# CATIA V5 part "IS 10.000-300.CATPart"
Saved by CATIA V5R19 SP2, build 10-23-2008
Part number: IS 10.000-300
Bounding box of the stored display mesh (mm): x -97.324 to 97.324, y -97.5 to 97.5, z 0 to 760
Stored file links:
  C:\Users\Bora\Desktop\3D Katı model\IS serisi\IS 10.000\IS 10.000-300.CATPart
  C:\Program Files\Dassault Systemes\B19\intel_a\reffiles\standard\MetricThickPitch.txt
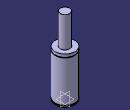
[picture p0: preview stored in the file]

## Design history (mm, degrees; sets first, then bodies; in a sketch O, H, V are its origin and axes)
Body1 (main body)
  Sketch1 on yz-plane, origin (0, 0, 0), H (0, 1, 0), V (0, 0, 1)
    point P1 (97.5, 429)
    point P4 (97.5, 424)
    point P7 (47.5, 759)
    point P9 (47.5, 759)
    point P13 (97.5, 429)
    point P14 (97.5, 424)
    line L1 (97.5, 429) -> (97.5, 457)
    line L2 (97.5, 16) -> (97.5, 424)
    line L3 (93.5, 16) -> (93.5, 8)
    arc A1 centre (46.5, 759) radius 1 from (47.5, 759) to (46.5, 760) ccw
    line L4 (47.5, 759) -> (47.5, 457)
    line L5 (97.5, 0) -> (97.5, 8)
    arc A2 centre (97.5, 426.5) radius 2.5 from (97.5, 429) to (97.5, 424) ccw
    line L6 (46.5, 760) -> (0, 760)
    point P15 (0, 760)
    line L7 (47.5, 457) -> (97.5, 457)
    line L8 (93.5, 16) -> (97.5, 16)
    line L9 (93.5, 8) -> (97.5, 8)
    line L10 (97.5, 0) -> (0, 0)
    tangency: L6 A1
    coincidence: P15 V, P1 P13, P4 P14, P7 P9
    horizontal: L7 H, L8 H, L9 H, L10 H
  Shaft1: profile Sketch1, axis Sketch1.V, angle 360
  Sketch2 on face of Shaft1 from Sketch1.L10, origin (0, 0, 0), H (1, 0, 0), V (0, -1, 0)
    point P1 (60, 0)
    distance P1 V = 60
  Hole1: placed by Sketch2, at (60, 0, 0) direction (0, 0, 1), diameter 10.106, depth 16, threaded "M12", thread diameter 12, thread depth 16, pitch 1.75
  CircPattern1: of Hole1, instances 4, angular step 90, axis from xy-plane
